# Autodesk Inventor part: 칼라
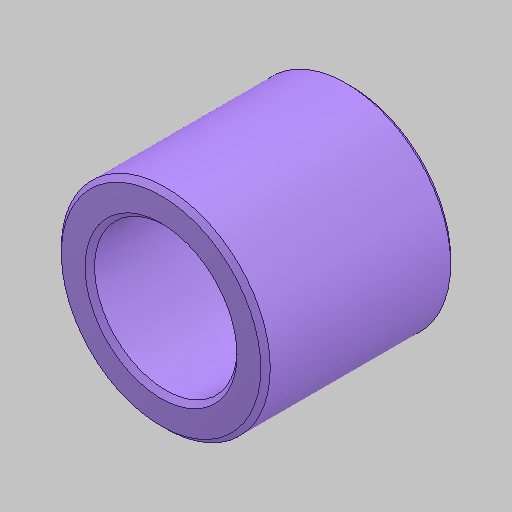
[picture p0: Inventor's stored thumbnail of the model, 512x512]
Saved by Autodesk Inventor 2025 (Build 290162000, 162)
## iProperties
Created: 2024-07
Part Number: 칼라
Material: 스테인리스강
Document SubType Name: Modeling
Designer: 현기
Density: 8.08 g/cm^3
Appearance: 기본값
Author: jhkim
Sending System: Autodesk Inventor 2025
Preprocessor: ST-DEVELOPER v20
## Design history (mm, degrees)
feature "솔리드1"
node "솔리드2"
